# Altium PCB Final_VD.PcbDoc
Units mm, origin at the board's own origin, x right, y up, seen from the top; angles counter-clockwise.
Board outline 30.35 x 16.46 mm, 2 copper layers (Top Layer, Bottom Layer), stack 1.671 mm thick; 33 components, 51 nets, 121 pads, 75 vias.
Unrouted connection lines stored in the file: 42.
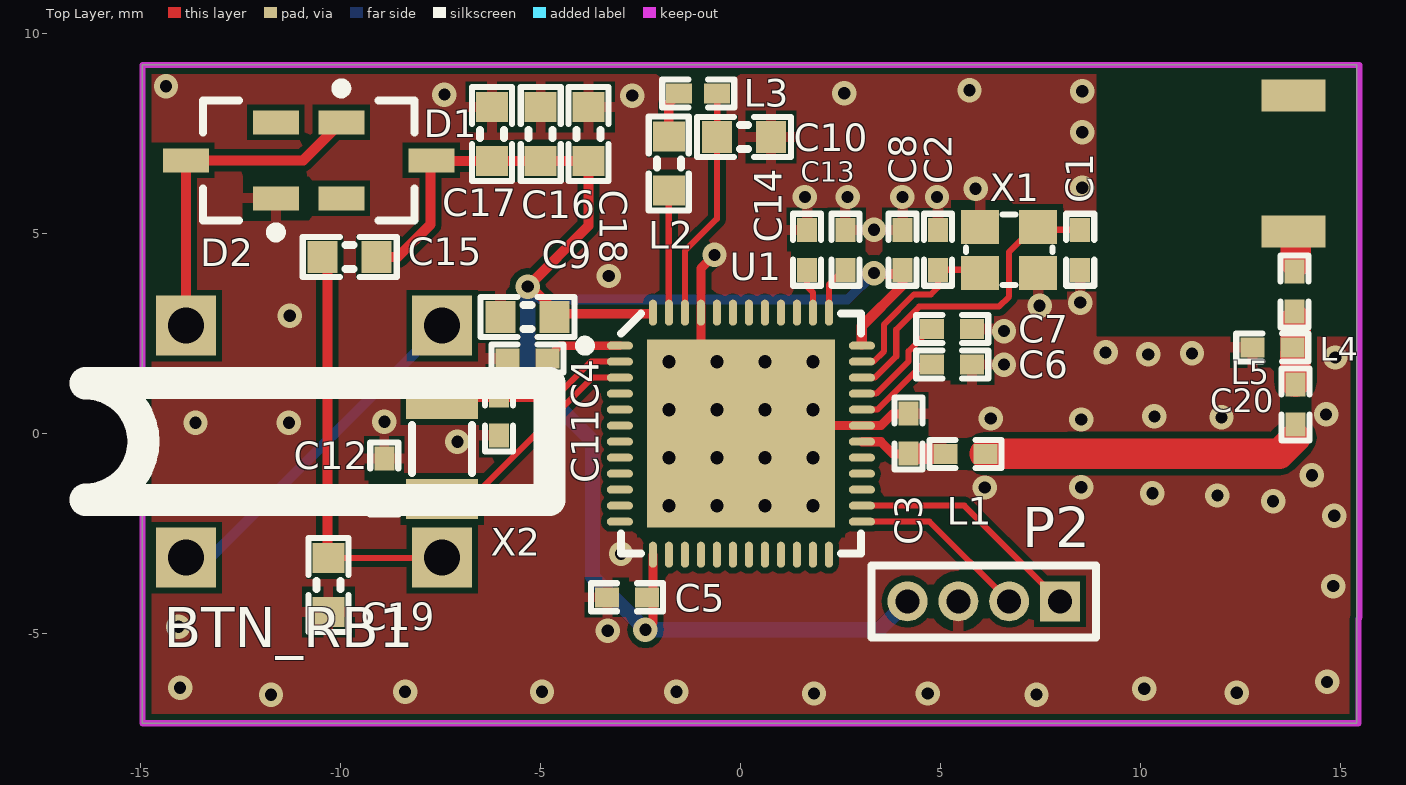
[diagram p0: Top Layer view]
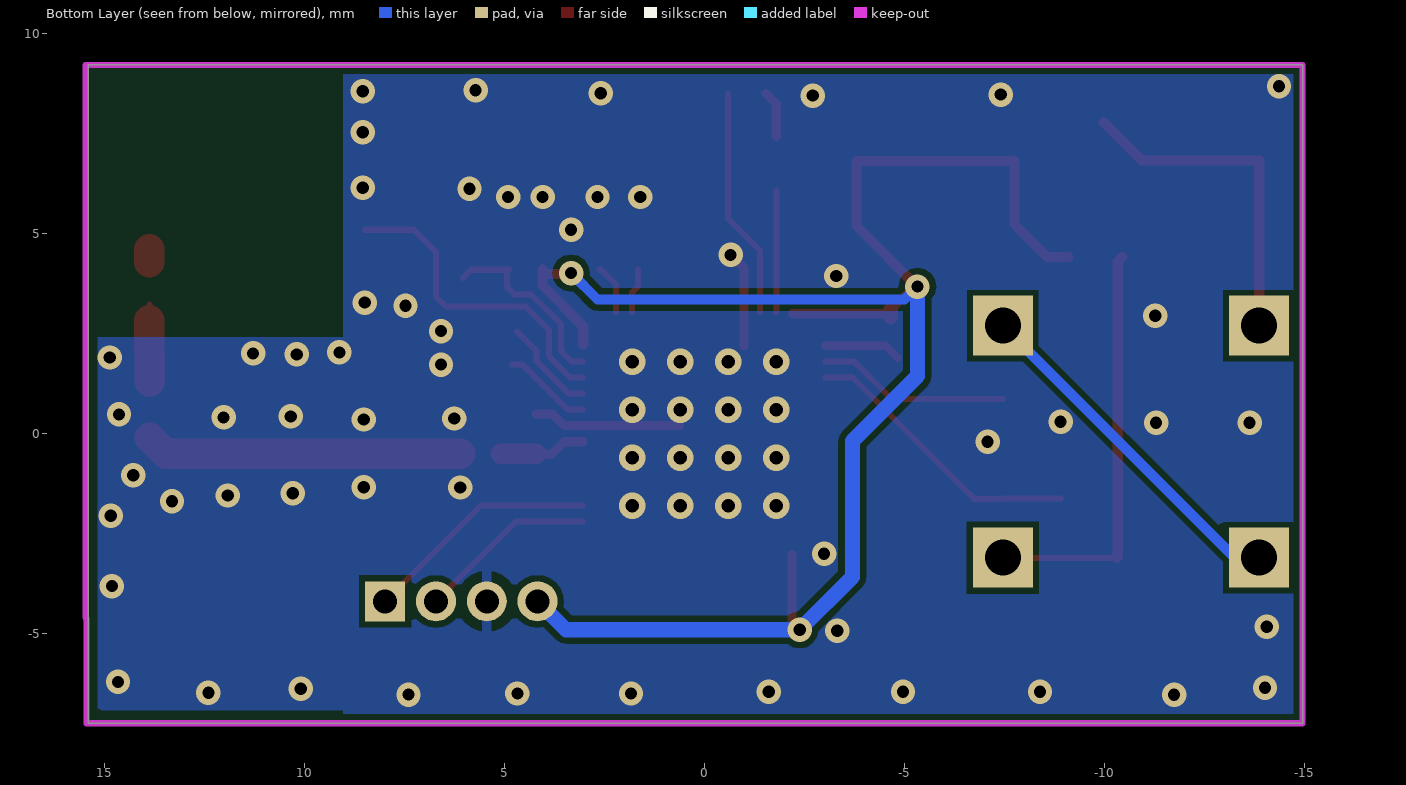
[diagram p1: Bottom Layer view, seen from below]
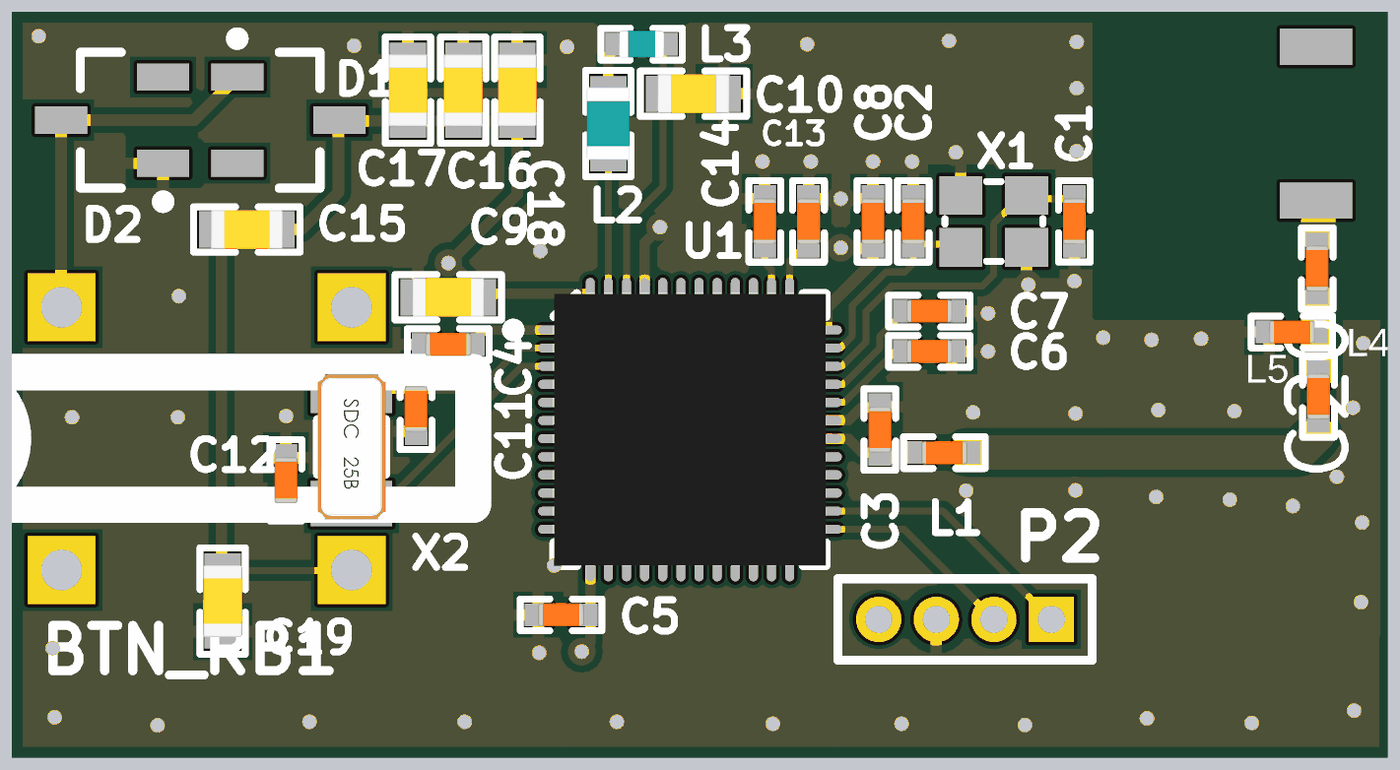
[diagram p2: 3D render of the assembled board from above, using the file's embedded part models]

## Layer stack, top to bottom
Top Solder: solder mask 0.0102, Solder Resist, Dk 3.5
Top Layer: signal copper 0.0356
Dielectric1: core 1.6002, FR-4, Dk 4.8
Bottom Layer: signal copper 0.0356
Bottom Solder: solder mask 0.0102, Solder Resist, Dk 3.5

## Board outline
-14.961,-7.239 -14.961,9.22 15.392,9.22 15.392,-7.239

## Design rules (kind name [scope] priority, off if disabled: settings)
Clearance Polygon_ANT [(InNamedPolygon('Top_Layer-GND')) or (InNamedPolygon('Bottom_Layer-GND')) vs InNet('RF')] p1: gap=0.127 ignorepadtopadclearanceinfootprint=FALSE except(0: Arc-Hole Track-Hole SMDPad-Hole THPad-Hole Via-Hole Fill-Hole Poly-Hole Region-Hole Text-Hole)
Clearance Polygon [(InNamedPolygon('Top_Layer-GND')) or (InNamedPolygon('Bottom_Layer-GND'))] p2: gap=0.254 ignorepadtopadclearanceinfootprint=FALSE except(0: Arc-Hole Track-Hole SMDPad-Hole THPad-Hole Via-Hole Fill-Hole Poly-Hole Region-Hole Text-Hole)
Clearance [All] p3: gap=0.152 ignorepadtopadclearanceinfootprint=FALSE except(0: Arc-Hole Track-Hole SMDPad-Hole THPad-Hole Via-Hole Fill-Hole Poly-Hole Region-Hole Text-Hole)
ComponentClearance [All] p1 off: gap=0.254 collisioncheckmode=3 verticalgap=0.254 showdistances=FALSE
FabricationTestPointUsage TestPointUsage [All] p1: valid=0 allowmultiple=FALSE
FabricationTestpoint Testpoint [All] p1: side=3 testpointundercomponent=TRUE minsize=1.016 maxsize=2.54 preferedsize=1.524 minholesize=0 maxholesize=1.016 preferedholesize=0.813 testpointgrid=0.025 allowsidetop=TRUE allowsidebottom=TRUE usegrid=TRUE gridtolerance=0
Height [All] p1 off: minheight=0 maxheight=25.4 prefheight=12.7
HoleSize [All] p1: absolutevalues=TRUE maxlimit=4.064 minlimit=0.305 maxpercent=80.000 minpercent=20.000
MinimumAnnularRing [All] p1 off: minimumring=0.152
PolygonConnect PolygonConnect_1 [isVia and innet(gnd)] p1: connectstyle=Direct reliefconductorwidth=0.254 reliefentries=4 polygonreliefangle="90 Angle" airgapwidth=0.254
PolygonConnect [All] p2: connectstyle=Relief reliefconductorwidth=0.254 reliefentries=4 polygonreliefangle="90 Angle" airgapwidth=0.254
RoutingVias [All] p1: holewidth=0.406 width=0.813 viastyle="Through Hole" minholewidth=0.254 minwidth=0.254 maxholewidth=0.711 maxwidth=1.27
SilkToSolderMaskClearance SilkscreenOverComponentPads [IsPad] p1: minsilkscreentomaskgap=0.254 clearancetoexposedcopper=TRUE
SolderMaskExpansion [All] p1: expansion=0.076
Width [All] p1: maxlimit=2.54 minlimit=0.152 preferedwidth=0.152
24 further rules are at their usual default settings.

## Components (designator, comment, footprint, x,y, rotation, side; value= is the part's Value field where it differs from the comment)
BTN_RB1 "ZF_button" ZF-button -13.868,2.701 r0 top
C1 "12pF" CAPC1005X04L 8.483,4.598 r270 top
C2 "12pF" CAPC1005X04L 4.927,4.598 r90 top
C3 "0.8pF" CAPC1005X04L 4.191,0 r270 top
C4 "100nF" CAPC1005X04L -5.334,1.88 r180 top
C5 "100nF" CAPC1005X04L -2.845,-4.089 r180 top
C6 "N.C." CAPC1005X04L 5.283,1.727 r180 top
C7 "100pF" CAPC1005X04L 5.283,2.616 r0 top
C8 "100nF" CAPC1005X04L 4.038,4.598 r90 top
C9 "4.7µF" CAPC1608X06L -5.334,2.921 r180 top
C10 "1.0µF" CAPC1608X06L 0.076,7.417 r180 top
C11 "12pF" CAPC1005X04L -6.045,0.457 r270 top
C12 "12pF" CAPC1005X04L -8.915,-1.118 r90 top
C13 "12pF" CAPC1005X04L 2.616,4.598 r90 top
C14 "12pF" CAPC1005X04L 1.651,4.598 r90 top
C15 "47µF" CAPC1608X06L -9.779,4.42 r0 top
C16 "10µF" CAPC1608X06L -5.004,7.493 r270 top
C17 "10µF" CAPC1608X06L -6.223,7.493 r270 top
C18 "10µF" CAPC1608X06L -3.81,7.493 r270 top
C19 "220µF" CAPC1608X06L -10.312,-3.785 r90 top
C20 "Cap" CAPC1005X04L 13.868,0.732 r90 top value=12pF
D1 "Diode 1N4004" SOT-23_N -8.865,6.833 r0 top
D2 "Diode 1N4004" SOT-23_N -12.751,6.833 r180 top
E "Antenna" antenne 13.818,6.756 r90 top
L1 "3.9nH" CAPC1005X04L 5.613,-0.508 r0 top
L2 "10µH" INDC1608X06L -1.803,6.756 r270 top
L3 "15nH" INDC1005X04L -1.067,8.509 r180 top
L4 "3.3nH" CAPC1005X04L 13.842,3.558 r90 top value=3.9nH
L5 "2.7nH" CAPC1005X04L 13.284,2.155 r180 top value=3.9nH
P2 "MHDR1X4" MHDR1X4 7.976,-4.191 r180 top
U1 "nRF52832-QFAA" QFN40P600X600X90-48N 0,0 r0 top locked
X1 "32MHz" BT-XTAL_2016 6.705,4.598 r180 top
X2 "32.768kHz" XTAL_3215 -7.468,-0.381 r270 top

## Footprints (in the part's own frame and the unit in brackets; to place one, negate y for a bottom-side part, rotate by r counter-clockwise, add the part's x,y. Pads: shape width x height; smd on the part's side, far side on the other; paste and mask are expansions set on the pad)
antenne [mm]
  rect 0.8x1.6 smd: 1(-1.7,0) 2(1.7,0)
BT-XTAL_2016 [mm] "Crystal 2.0 x 1.6 mm"
  rect 0.95x0.85 smd: 1(-0.725,-0.575) 2(0.725,-0.575) 3(0.725,0.575) 4(-0.725,0.575)
  silkscreen extent -1.08,-0.88 1.08,0.88
CAPC1005X04L [mm] "Chip Capacitor, 2-Leads, Body 1.0x0.5mm, IPC High Density"
  rect 0.6x0.5 smd: 1(-0.5,0) 2(0.5,0)
  silkscreen extent -0.9,-0.35 0.9,0.35, body extent -0.51,-0.25 0.51,0.25, height 0.5
CAPC1608X06L [mm] "Chip Capacitor, 2-Leads, Body 1.6x0.8mm, IPC High Density"
  rect 0.75x0.8 smd: 1(-0.675,0) 2(0.675,0)
  silkscreen extent -1.17,-0.5 1.17,0.5, body extent -0.8,-0.43 0.8,0.43, height 0.8
INDC1005X04L [mm] "Chip Inductor, 2-Leads, Body 1.0x0.5mm, IPC High Density"
  rect 0.65x0.5 smd: 1(-0.475,0) 2(0.475,0)
  silkscreen extent -0.9,-0.35 0.9,0.35, body extent -0.5,-0.3 0.5,0.3, height 0.5
INDC1608X06L [mm] "Chip Inductor, 2-Leads, Body 1.6x0.8mm, IPC High Density"
  rect 0.75x0.8 smd: 1(-0.675,0) 2(0.675,0)
  silkscreen extent -1.18,-0.5 1.17,0.5, body extent -0.8,-0.48 0.8,0.48, height 0.8
MHDR1X4 [mm] "Connector; Header; 4 Position"
  rect 1x1 hole 0.6: 1(0,0)
  round 1 hole 0.6: 2(1.27,0) 3(2.54,0) 4(3.81,0)
  silkscreen extent -0.9,-0.9 4.71,0.9
QFN40P600X600X90-48N [mm] "QFN, 48-Leads, Body 6,0x6,0mm (max), Pitch 0,40mm, IPC Medium Density"
  oval 0.65x0.2 smd: 1(-3.025,2.2) 2(-3.025,1.8) 3(-3.025,1.4) 4(-3.025,1) 5(-3.025,0.6) 6(-3.025,0.2) 7(-3.025,-0.2) 8(-3.025,-0.6) 9(-3.025,-1) 10(-3.025,-1.4) 11(-3.025,-1.8) 12(-3.025,-2.2) 25(3.025,-2.2) 26(3.025,-1.8) 27(3.025,-1.4) 28(3.025,-1) 29(3.025,-0.6) 30(3.025,-0.2) 31(3.025,0.2) 32(3.025,0.6) 33(3.025,1) 34(3.025,1.4) 35(3.025,1.8) 36(3.025,2.2)
  oval 0.2x0.65 smd: 13(-2.2,-3.025) 14(-1.8,-3.025) 15(-1.4,-3.025) 16(-1,-3.025) 17(-0.6,-3.025) 18(-0.2,-3.025) 19(0.2,-3.025) 20(0.6,-3.025) 21(1,-3.025) 22(1.4,-3.025) 23(1.8,-3.025) 24(2.2,-3.025) 37(2.2,3.025) 38(1.8,3.025) 39(1.4,3.025) 40(1,3.025) 41(0.6,3.025) 42(0.2,3.025) 43(-0.2,3.025) 44(-0.6,3.025) 45(-1,3.025) 46(-1.4,3.025) 47(-1.8,3.025) 48(-2.2,3.025)
  rect 4.7x4.7 smd: 49(0,0)
  silkscreen extent -4.02,-3 3,3, body extent -3.02,-3.02 3.02,3.02, height 0.86
SOT-23_N [mm] "SOT23, 3-Leads, Body 2.9x1.3mm, Pitch 0.95mm, Lead Span 2.5mm, IPC Medium Density"
  rect 1.15x0.6 smd: 1(-1.125,0.95) 2(-1.125,-0.95) 3(1.125,0)
  silkscreen extent -1.25,-1.5 0.7,1.92, body extent -0.7,-1.5 0.7,1.5, height 1.1
XTAL_3215 [mm] "XTAL SMD 3.2 x 1.5 mm"
  rect 1x1.8 smd: 1(-1.25,0) 2(1.25,0)
  silkscreen extent -0.6,-0.75 0.6,0.75, body extent -1.6,-0.75 1.6,0.75, height 0.81
ZF-button [mm]
  rect 1.5x1.5 hole 0.9: 1(0,0) 2(0,-5.8) 3(6.4,-5.8) 4(6.4,0)
  silkscreen extent -2.52,-4.36 9.08,-1.43

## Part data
C1 C2 C11 C12 C13 C14: library part C0402-12p, "Capacitor, NP0, ±2%"
C3: library part C0402-0.8p, "Capacitor, NP0, ±5%"
C4 C5 C8: library part C0402-100n, "Capacitor, X7R, ±10%"
C6: library part C0402-N.C., "Not mounted"
C7: library part C0402-100p, "Capacitor, NP0, ±5%"
C9: library part C0603-4µ7, "Capacitor, X5R, ±10%"
C10: library part C0603-1µ0, "Capacitor, X7R, ±10%"
C15 C16 C17 C18 C19: "Capacitor, X5R, ±10%", Part Number=C0603-4µ7
C20: "Capacitor"
D1 D2: "1 Amp General Purpose Rectifier"
E: "Generic Antenna"
L1 L4 L5: library part L0402-3n9, "High frequency chip inductor ±5%", Manufacturer=Murata, Manufacturer Part Number=LQP15MN3N9B02D, Supplier part number=490-1131-1-ND
L2: library part L0603-10µ, "Chip inductor, IDC,min = 50 mA, ±20%", 2nd source part number=178-6105, Manufacturer="Taiyo Yuden", Manufacturer Part Number=LBMF1608T100K, Supplier part number=587-1714-1-ND
L3: library part L0402-15n, "High frequency chip inductor ±10%", 2nd source part number=658-1328, Manufacturer="Taiyo Yuden", Manufacturer Part Number=HK100515NJ-T, Supplier part number=587-1521-1-ND
P2: "Header, 4-Pin"
U1: "Multi-protocol Bluetooth Low Energy, ANT and 2.4GHz proprietary system-on-chip", Manufacturer="Nordic Semiconductor"
X1: library part XTAL_SMD2016_32MHz_8pF_General, "XTAL SMD 2016, 32MHz, Cl=8pF, Total Tol: ±40ppm"
X2: library part XTAL_SMD3215_32.768kHz_9pF_General, "XTAL SMD 3215, 32.768kHz, Cl=9pF, Total Tol: ±50ppm"

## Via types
v1: diameter 0.61, hole 0.305, Top Layer to Bottom Layer, tented both sides, 59 vias
v2: diameter 0.66, hole 0.33, Top Layer to Bottom Layer, tented both sides, 16 vias

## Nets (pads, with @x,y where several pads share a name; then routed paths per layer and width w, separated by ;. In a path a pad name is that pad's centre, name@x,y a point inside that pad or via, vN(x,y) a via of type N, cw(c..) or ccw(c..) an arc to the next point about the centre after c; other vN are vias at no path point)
DEC1: C4.1 U1.1 | length 1.9
  Top Layer w0.203: C4.1@-4.83,1.899 -4.529,2.2 U1.1
DEC2: C6.2 U1.32 | length 2.2
  Top Layer w0.152: U1.32 3.411,0.6 4.538,1.727 C6.2@4.801,1.727
DEC3: C7.1 U1.33 | length 2.4
  Top Layer w0.152: U1.33 3.38,1 4.191,1.811 4.191,2.062 C7.1@4.675,2.546
DEC4: C10.2 L3.1 U1.46 | length 5.8
  Top Layer w0.152: U1.46 -1.4,4.569 -0.599,5.37 C10.2 -0.592,7.424 L3.1
GND: C1.2 C2.2 C3.1 C4.2 C5.2 C6.1 C7.2 C8.2 C9.2 C10.1 C11.2 C12.2 C13.2 C14.2 C16.1 C17.1 C18.1 C19.1 D2.1 L5.2 P2.3 U1.31 U1.45 U1.49 X1.2 X1.4 | length 6.1
  Top Layer w0.229: U1.49@-1,2.2 U1.45 -1,4.131 v1(-0.66,4.47) ; U1.49@0.618,0.203 3.499,0.203 3.786,0.49 C3.1@4.199,0.49
  other v1: -11.747,-6.528 7.391,-6.522 1.829,-6.495 4.67,-6.495 12.395,-6.477 -8.395,-6.452 -4.971,-6.452 -1.613,-6.452 10.084,-6.376 -14.021,-6.35 14.656,-6.205 -3.327,-4.928 -14.063,-4.826 14.808,-3.81 -2.997,-3 14.834,-2.053 13.304,-1.687 11.913,-1.545 10.287,-1.488 6.096,-1.346 8.509,-1.34 14.275,-1.041 -7.087,-0.203 -13.636,0.273 -11.299,0.273 -8.911,0.299 8.509,0.356 6.248,0.381 12.014,0.406 10.338,0.432 14.63,0.483 6.579,1.727 14.859,1.905 10.185,1.981 11.278,2.007 9.119,2.032 6.579,2.565 -11.278,2.946 7.468,3.2 8.483,3.277 -3.302,3.942 3.327,5.098 1.6,5.918 2.667,5.918 4.039,5.918 4.902,5.918 5.867,6.122 8.534,6.147 8.534,7.537 -2.714,8.452 -7.413,8.478 2.586,8.509 8.534,8.56 5.715,8.585 -14.372,8.687
  other v2: -1.8,-1.8 -0.6,-1.8 0.6,-1.8 1.8,-1.8 -1.8,-0.6 -0.6,-0.6 0.6,-0.6 1.8,-0.6 -1.8,0.6 -0.6,0.6 0.6,0.6 1.8,0.6 -1.8,1.8 -0.6,1.8 0.6,1.8 1.8,1.8
NetBTN_RB1_1: BTN_RB1.1 D1.1 D2.3 | length 8.4
  Top Layer w0.254: BTN_RB1.1 -13.876,2.709 D2.3 -10.94,6.833 D1.1
NetBTN_RB1_2: BTN_RB1.2 BTN_RB1.4 | length 8.8
  Bottom Layer w0.254: BTN_RB1.2 -13.268,-3.099 BTN_RB1.4
NetBTN_RB1_3: BTN_RB1.3 C15.1 C19.2 | length 10.4
  Top Layer w0.152: C19.2 -7.478,-3.11 BTN_RB1.3
  Top Layer w0.254: C15.1 -10.338,4.303 -10.338,-3.084 C19.2
NetC3_2: C3.2 L1.1 U1.30 | length 2.2
  Top Layer w0.229: U1.30 3.5,-0.2 3.81,-0.51 C3.2@4.199,-0.51
  Top Layer w0.508: C3.2@4.191,-0.505 L1.1@5.088,-0.505
NetC20_2: C20.2 L4.1 L5.1 | length 2.6
  Top Layer w0.152: L5.1@13.868,2.147 13.86,2.155 13.868,2.163 L4.1@13.868,3.234
  Top Layer w0.762: C20.2@13.86,1.297 L4.1@13.868,2.838
NetE_1: E.1 L4.2 | length 0.3
  Top Layer w0.762: L4.2@13.868,4.283 13.868,4.613
NetL2_1: L2.1 L3.2 | length 1.2
  Top Layer w0.229: L2.1 -1.803,8.247 L3.2
NetL2_2: L2.2 U1.47 | length 3.1
  Top Layer w0.152: L2.2 -1.803,3.028 U1.47
P0.00/XL1: C11.1 U1.2 X2.1 | length 4.8
  Top Layer w0.152: X2.1 -4.683,0.869 -3.752,1.8 U1.2
P0.01/XL2: C12.1 U1.3 X2.2 | length 7.2
  Top Layer w0.152: C12.1 -7.481,-1.618 X2.2 -6.787,-1.631 -6.782,-1.626 -6.746,-1.626 -3.721,1.4 U1.3
P0.02/AIN0: U1.4
P0.03/AIN1: U1.5
P0.04/AIN2: U1.6
P0.05/AIN3: U1.7
P0.06: U1.8
P0.07: U1.9
P0.08: U1.10
P0.09: U1.11
P0.10: U1.12
P0.11: U1.14
P0.12: U1.15
P0.13: U1.16
P0.14: U1.17
P0.15: U1.18
P0.16: U1.19
P0.17: U1.20
P0.18: U1.21
P0.19: U1.22
P0.20: U1.23
P0.21: U1.24
P0.22: U1.27
P0.23: U1.28
P0.24: U1.29
P0.25: C13.1 U1.37 | length 1.3
  Top Layer w0.152: U1.37 2.2,3.724 2.595,4.119 C13.1
P0.26: C14.1 U1.38 | length 1.1
  Top Layer w0.152: C14.1 1.651,3.683 1.8,3.534 U1.38
P0.27: U1.39
P0.28/AIN4: U1.40
P0.29/AIN5: U1.41
P0.30/AIN6: U1.42
P0.31/AIN7: U1.43
RF: C20.1 L1.2 | length 8.3
  Top Layer w0.762: L1.2@6.096,-0.502 8.509,-0.502 ; 8.153,-0.502 13.458,-0.502 13.86,-0.099
SWDCLK: P2.2 U1.25 | length 4.5
  Top Layer w0.152: U1.25 4.715,-2.2 P2.2
SWDIO: P2.1 U1.26 | length 5.9
  Top Layer w0.152: U1.26 5.585,-1.8 P2.1
VDD_NRF: C5.1 C8.1 C9.1 C15.2 C16.2 C17.2 C18.2 D1.3 P2.4 U1.13 U1.36 U1.48 | length 45.2
  Top Layer w0.229: v1(-5.33,3.677) -5.247,3.677 -4.655,3.085 -4.57,3 U1.48@-2.21,3 ; v1(-2.388,-4.902) -2.2,-4.715 U1.13
  Top Layer w0.254: C15.2 -8.571,4.42 -7.758,5.232 -7.758,6.814 D1.3 -7.725,6.818 C17.2 C16.2 C18.2 -3.81,5.197 v1(-5.33,3.677) ; U1.36@3.023,2.227 3.023,2.688 4.038,3.704 C8.1 ; v1(3.327,4.013) 3.345,3.996 C8.1@4.038,3.996
  Top Layer w0.381: C9.1@-4.655,2.915 C9.1@-4.655,3.085
  Bottom Layer w0.254: v1@-5.33,3.674 v1(-5.33,3.677) -5.006,3.353 2.667,3.353 v1(3.327,4.013)
  Bottom Layer w0.381: v1@-5.33,3.674 -5.33,1.439 -3.707,-0.184 -3.707,-3.583 v1(-2.388,-4.902) 3.454,-4.902 P2.4
XC1: C1.1 U1.34 X1.1 | length 8
  Top Layer w0.152: U1.34 3.349,1.4 3.883,1.934 3.883,2.603 4.456,3.175 6.451,3.175 6.705,3.429 6.705,4.547 7.256,5.098 C1.1
XC2: C2.1 U1.35 X1.3 | length 4.7
  Top Layer w0.152: U1.35 3.315,1.8 3.579,2.064 3.579,2.733 4.326,3.48 4.75,3.48 4.927,3.657 C2.1@4.927,4.09 ; C2.1@4.877,4.098 5.833,4.098 X1.3@6.033,3.898
pads on no net: D1.2 D2.2 E.2 U1.44

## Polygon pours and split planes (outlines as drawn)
no net on Bottom Layer "Bottom Layer-No Net" (solid, pour order 24): 12.598,-2
no net on Bottom Layer "Bottom Layer-No Net 1" (solid, pour order 22): 12.167,-2.718
GND on Bottom Layer "Bottom Layer-GND" (solid, pour order 20): 8.915,2.362 8.966,2.413 15.164,2.413 15.164,-7.006 15.066,-6.909 8.915,-6.909
GND on Bottom Layer "GND" (solid, pour order 16): 9.093,9.195 9.017,9.119 9.017,-7.137 -14.91,-7.137 -14.961,-7.188 -14.961,9.195
GND on Top Layer "Top Layer-GND" (solid, pour order 18): 8.886,9.119 8.886,2.455 8.919,2.421 15.451,2.421 15.418,2.388 15.418,-7.188 -14.91,-7.188 -14.859,-7.137 -14.859,9.119

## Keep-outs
Keep-Out Layer:
  lines w0.152: -14.961,-7.239 -14.961,9.22 13.995,9.22 15.469,9.22 15.469,6.579 15.469,-4.597 15.443,-4.623 15.443,-7.239 -14.961,-7.239

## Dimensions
18.669,9.22 to 17.628,-7.264 on Top Layer
-14.961,9.703 to 15.469,12.725 on Top Layer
